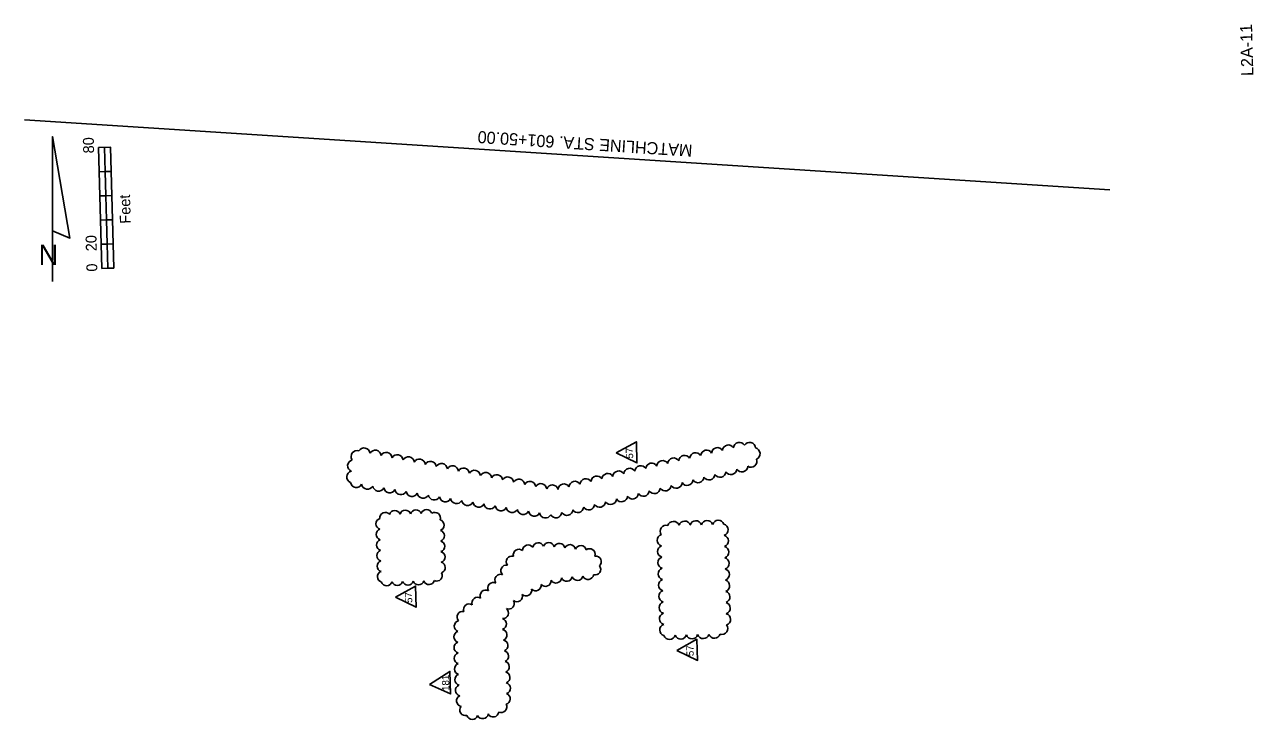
# Model space of a CAD drawing. Extents: x 928638 to 929505, y 634823 to 636085.
# Drawn here: x 928638 to 929451, y 635624 to 636085 of the extents above; entities that cross this region are included whole.
import ezdxf

# ---------------------------------------------------------------- set-up
doc = ezdxf.new("R2010")
doc.units = 0
for name, color, linetype in [('Cloud_dp', 7, 'Continuous'), ('MatchLines_dp', 7, 'Continuous'), ('NorthArw_dp', 7, 'Continuous'), ('Scale_dp', 7, 'Continuous'), ('TextShtNo', 7, 'Continuous')]:
    doc.layers.add(name, color=color, linetype=linetype)

msp = doc.modelspace()

# ---------------------------------------------------------------- linework, layer by layer
at = {"layer": 'Cloud_dp'}
for points in [[(929029.47, 635800.9), (929043.22, 635794.23), (929042.84, 635808.31)], [(928883.23, 635705.29), (928896.98, 635698.62), (928896.6, 635712.7)], [(929069.55, 635670.07), (929083.3, 635663.4), (929082.91, 635677.48)], [(928905.8, 635647.39), (928919.81, 635641.24), (928919.41, 635656.14)]]:
    msp.add_lwpolyline(points, close=True, dxfattribs=at)
for centre, radius, start, end in [((929111.02, 635803.95), 3.91, 30.8103, 175.8103), ((929117.72, 635803.92), 3.91, 3.63215, 148.63215), ((928857.83, 635798.47), 3.91, 70.45353, 215.45353), ((928862.57, 635800.26), 3.91, 6.08636, 151.08636), ((928869.88, 635798.79), 3.91, 6.08636, 151.08636), ((928877.2, 635797.31), 3.91, 6.08636, 151.08636), ((928884.51, 635795.83), 3.91, 6.08636, 151.08636), ((929081.97, 635797.08), 3.91, 30.8103, 175.8103), ((929089.24, 635798.79), 3.91, 30.8103, 175.8103), ((929096.5, 635800.51), 3.91, 30.8103, 175.8103), ((929103.76, 635802.23), 3.91, 30.8103, 175.8103), ((929120.8, 635800.34), 3.91, 292.8347, 77.8347), ((928855.54, 635792.39), 3.91, 103.22978, 248.22978), ((928891.82, 635794.36), 3.91, 6.08636, 151.08636), ((928899.14, 635792.88), 3.91, 6.08636, 151.08636), ((928906.45, 635791.4), 3.91, 6.08636, 151.08636), ((928913.77, 635789.93), 3.91, 6.08636, 151.08636), ((928921.08, 635788.45), 3.91, 6.08636, 151.08636), ((929045.67, 635788.49), 3.91, 30.8103, 175.8103), ((929052.93, 635790.2), 3.91, 30.8103, 175.8103), ((929060.19, 635791.92), 3.91, 30.8103, 175.8103), ((929067.45, 635793.64), 3.91, 30.8103, 175.8103), ((929074.71, 635795.36), 3.91, 30.8103, 175.8103), ((929112.64, 635792.24), 3.91, 211.47427, 356.47427), ((929118.68, 635795.28), 3.92, 236.84141, 21.84141), ((928854.99, 635784.95), 3.91, 103.22978, 248.22978), ((928928.39, 635786.97), 3.91, 6.08636, 151.08636), ((928935.71, 635785.5), 3.91, 6.08636, 151.08636), ((928943.02, 635784.02), 3.91, 6.08636, 151.08636), ((928950.34, 635782.54), 3.91, 6.08636, 151.08636), ((928957.65, 635781.07), 3.91, 6.08636, 151.08636), ((928964.97, 635779.59), 3.91, 6.08636, 151.08636), ((929009.36, 635779.9), 3.91, 30.8103, 175.8103), ((929016.62, 635781.62), 3.91, 30.8103, 175.8103), ((929023.88, 635783.33), 3.91, 30.8103, 175.8103), ((929031.15, 635785.05), 3.91, 30.8103, 175.8103), ((929038.41, 635786.77), 3.91, 30.8103, 175.8103), ((929083.67, 635785.04), 3.91, 211.47427, 356.47427), ((929090.91, 635786.84), 3.91, 211.47427, 356.47427), ((929098.15, 635788.64), 3.91, 211.47427, 356.47427), ((929105.39, 635790.44), 3.91, 211.47427, 356.47427), ((928857.41, 635781.88), 3.91, 188.32723, 333.32723), ((928864.77, 635780.69), 3.91, 188.32723, 333.32723), ((928872.14, 635779.5), 3.91, 188.32723, 333.32723), ((928879.51, 635778.32), 3.91, 188.32723, 333.32723), ((928886.87, 635777.13), 3.91, 188.32723, 333.32723), ((928894.24, 635775.94), 3.91, 188.32723, 333.32723), ((928972.28, 635778.11), 3.91, 6.08636, 151.08636), ((928979.59, 635776.64), 3.91, 6.08636, 151.08636), ((928987.16, 635775.72), 3.91, 15.15981, 160.15981), ((928994.84, 635776.46), 3.91, 30.8103, 175.8103), ((929002.1, 635778.18), 3.91, 30.8103, 175.8103), ((929047.47, 635776.03), 3.91, 211.47427, 356.47427), ((929054.71, 635777.83), 3.91, 211.47427, 356.47427), ((929061.95, 635779.63), 3.91, 211.47427, 356.47427), ((929069.19, 635781.43), 3.91, 211.47427, 356.47427), ((929076.43, 635783.24), 3.91, 211.47427, 356.47427), ((928901.61, 635774.75), 3.91, 188.32723, 333.32723), ((928908.97, 635773.56), 3.91, 188.32723, 333.32723), ((928916.34, 635772.37), 3.91, 188.32723, 333.32723), ((928923.7, 635771.18), 3.91, 188.32723, 333.32723), ((928931.07, 635769.99), 3.91, 188.32723, 333.32723), ((928938.44, 635768.8), 3.91, 188.32723, 333.32723), ((928945.8, 635767.61), 3.91, 188.32723, 333.32723), ((929018.5, 635768.82), 3.91, 211.47427, 356.47427), ((929025.75, 635770.62), 3.91, 211.47427, 356.47427), ((929032.99, 635772.42), 3.91, 211.47427, 356.47427), ((929040.23, 635774.23), 3.91, 211.47427, 356.47427), ((928876.53, 635757.74), 3.67, 40.04927, 185.04927), ((928882.88, 635759.09), 3.68, 19.06552, 164.06552), ((928889.88, 635759.29), 3.68, 19.06552, 164.06552), ((928896.89, 635759.48), 3.68, 19.06552, 164.06552), ((928903.9, 635759.67), 3.68, 19.06552, 164.06552), ((928909.43, 635757.83), 3.67, 339.04988, 124.04988), ((928953.17, 635766.42), 3.91, 188.32723, 333.32723), ((928960.53, 635765.23), 3.91, 188.32723, 333.32723), ((928967.9, 635764.04), 3.91, 188.32723, 333.32723), ((928975.27, 635762.85), 3.91, 188.32723, 333.32723), ((928982.63, 635761.66), 3.91, 188.32723, 333.32723), ((928989.56, 635761.79), 3.91, 208.82569, 353.82569), ((928996.78, 635763.41), 3.91, 211.47427, 356.47427), ((929004.02, 635765.22), 3.91, 211.47427, 356.47427), ((929011.26, 635767.02), 3.91, 211.47427, 356.47427), ((928874.07, 635753.94), 3.68, 109.06552, 254.06552), ((928911.85, 635752.98), 3.68, 289.06552, 74.06552), ((929062.38, 635749.03), 3.89, 71.55935, 216.55935), ((929067.36, 635751.65), 3.89, 19.06552, 164.06552), ((929074.78, 635751.86), 3.89, 19.06552, 164.06552), ((929082.21, 635752.06), 3.89, 19.06552, 164.06552), ((929089.63, 635752.26), 3.89, 19.06552, 164.06552), ((929097.06, 635752.47), 3.89, 19.06552, 164.06552), ((929099.67, 635749.99), 3.89, 289.06552, 74.06552), ((928874.26, 635746.93), 3.68, 109.06552, 254.06552), ((928874.45, 635739.93), 3.68, 109.06552, 254.06552), ((928912.05, 635745.97), 3.68, 289.06552, 74.06552), ((929060.53, 635743.03), 3.89, 109.06552, 254.06552), ((929099.87, 635742.57), 3.89, 289.06552, 74.06552), ((928874.65, 635732.92), 3.68, 109.06552, 254.06552), ((928912.24, 635738.96), 3.68, 289.06552, 74.06552), ((928912.43, 635731.95), 3.68, 289.06552, 74.06552), ((928965.05, 635733.34), 3.72, 49.30078, 194.30078), ((928971.2, 635736.19), 3.72, 35.49184, 180.49184), ((928977.88, 635737.6), 3.72, 23.24379, 168.24379), ((928984.8, 635737.8), 3.72, 15.12111, 160.12111), ((928991.79, 635737.24), 3.72, 10.70177, 155.70177), ((928998.85, 635736.43), 3.72, 11.16897, 156.16897), ((929005.98, 635735.8), 3.72, 13.75882, 158.75882), ((929011.85, 635733.72), 3.72, 342.36262, 127.36262), ((929060.73, 635735.61), 3.89, 109.06552, 254.06552), ((929100.07, 635735.14), 3.89, 289.06552, 74.06552), ((928874.84, 635725.91), 3.68, 109.06552, 254.06552), ((928912.62, 635724.94), 3.68, 289.06552, 74.06552), ((928956.82, 635722.89), 3.72, 80.82709, 225.82709), ((928960.35, 635728.86), 3.72, 72.97795, 217.97795), ((929015.84, 635728.9), 3.72, 311.70815, 96.70815), ((929060.93, 635728.18), 3.89, 109.06552, 254.06552), ((929100.28, 635727.72), 3.89, 289.06552, 74.06552), ((928875.03, 635718.9), 3.68, 109.06552, 254.06552), ((928910.63, 635719.65), 3.67, 244.72719, 29.72719), ((928952.85, 635716.76), 3.72, 68.35857, 213.35857), ((928996.71, 635719.53), 3.72, 203.69742, 348.69742), ((929003.85, 635720.11), 3.72, 200.60291, 345.60291), ((929010.82, 635720.77), 3.72, 205.2281, 350.2281), ((929015.46, 635723.73), 3.72, 254.94433, 39.94433), ((929061.14, 635720.76), 3.89, 109.06552, 254.06552), ((929100.48, 635720.29), 3.89, 289.06552, 74.06552), ((928877.49, 635716.57), 3.68, 199.06552, 344.06552), ((928884.5, 635716.76), 3.68, 199.06552, 344.06552), ((928891.51, 635716.95), 3.68, 199.06552, 344.06552), ((928898.52, 635717.14), 3.68, 199.06552, 344.06552), ((928905.53, 635717.33), 3.68, 199.06552, 344.06552), ((928948.12, 635711.36), 3.72, 64.20736, 209.20736), ((928969.8, 635709.86), 3.72, 226.75654, 11.75654), ((928976.12, 635713.21), 3.72, 224.21089, 9.21089), ((928982.66, 635716.19), 3.72, 219.75189, 4.75189), ((928989.59, 635718.36), 3.72, 209.9442, 354.9442), ((929061.34, 635713.33), 3.89, 109.06552, 254.06552), ((929100.68, 635712.87), 3.89, 289.06552, 74.06552), ((928937.64, 635701.57), 3.72, 56.11517, 201.11517), ((928943.06, 635706.29), 3.72, 60.93764, 205.93764), ((928958.26, 635701.13), 3.72, 245.70709, 30.70709), ((928963.71, 635706), 3.72, 232.91799, 17.91799), ((929061.54, 635705.91), 3.89, 109.06552, 254.06552), ((929061.74, 635698.48), 3.89, 109.06552, 254.06552), ((929100.88, 635705.45), 3.89, 289.06552, 74.06552), ((928927.79, 635692.22), 3.72, 78.08417, 223.08417), ((928932.05, 635697.16), 3.72, 55.40174, 200.40174), ((928954.38, 635694.84), 3.72, 265.96014, 50.96014), ((929061.95, 635691.06), 3.89, 109.06552, 254.06552), ((929101.09, 635698.02), 3.89, 289.06552, 74.06552), ((929101.29, 635690.6), 3.89, 289.06552, 74.06552), ((928925.99, 635686.07), 3.72, 104.18139, 249.18139), ((928953.07, 635687.56), 3.72, 288.59197, 73.59197), ((929062.15, 635683.63), 3.89, 109.06552, 254.06552), ((929099.44, 635684.6), 3.89, 251.55935, 36.55935), ((928925.77, 635679.03), 3.72, 107.25231, 252.25231), ((928953.44, 635680.39), 3.72, 292.37351, 77.37351), ((929064.76, 635681.16), 3.89, 199.06552, 344.06552), ((929072.19, 635681.37), 3.89, 199.06552, 344.06552), ((929079.61, 635681.57), 3.89, 199.06552, 344.06552), ((929087.04, 635681.77), 3.89, 199.06552, 344.06552), ((929094.46, 635681.97), 3.89, 199.06552, 344.06552), ((928925.79, 635671.95), 3.72, 108.1911, 253.1911), ((928954.01, 635673.33), 3.72, 291.79029, 76.79029), ((928954.52, 635666.25), 3.72, 291.39534, 76.39534), ((928925.91, 635664.86), 3.72, 108.70236, 253.70236), ((928926.08, 635657.76), 3.72, 109.08693, 254.08693), ((928954.98, 635659.17), 3.72, 291.10502, 76.10502), ((928926.34, 635650.68), 3.72, 109.98189, 254.98189), ((928955.4, 635652.09), 3.72, 290.67805, 75.67805), ((928926.74, 635643.62), 3.72, 111.56299, 256.56299), ((928955.68, 635645.03), 3.72, 288.88082, 73.88082), ((928927.44, 635636.62), 3.72, 114.83706, 259.83706), ((928955.59, 635638.01), 3.72, 284.66878, 69.66878), ((928929.64, 635630.57), 3.73, 140.1104, 285.1104), ((928948.04, 635629.67), 3.73, 207.44055, 352.44055), ((928953.31, 635632.55), 3.72, 244.93463, 29.93463), ((928934.17, 635628.06), 3.72, 197.04995, 342.04995), ((928941.06, 635628.54), 3.72, 205.91527, 350.91527)]:
    msp.add_arc(centre, radius, start, end, dxfattribs=at)
at = {"layer": 'MatchLines_dp'}
msp.add_lwpolyline([(929356.28, 635975.21), (928997.02, 635998.35), (928637.76, 636021.48)], dxfattribs=at)
at = {"layer": 'NorthArw_dp'}
msp.add_line((928656.21, 635914.42), (928656.21, 636010.42), dxfattribs=at)
msp.add_lwpolyline([(928656.21, 635948.02), (928656.21, 636010.42), (928667.73, 635943.22)], close=True, dxfattribs=at)
at = {"layer": 'Scale_dp'}
for p, q in [((928694.72, 636003.32), (928686.73, 636003.1)), ((928686.73, 636003.1), (928688.91, 635923.13)), ((928696.91, 635923.35), (928694.72, 636003.32)), ((928688.91, 635923.13), (928696.91, 635923.35))]:
    msp.add_line(p, q, dxfattribs=at)
for points in [[(928695.16, 635987.32), (928691.16, 635987.21), (928690.73, 636003.21), (928694.72, 636003.32)], [(928691.6, 635971.22), (928687.6, 635971.11), (928687.17, 635987.1), (928691.16, 635987.21)], [(928696.04, 635955.33), (928692.04, 635955.23), (928691.6, 635971.22), (928695.6, 635971.33)], [(928692.47, 635939.23), (928688.48, 635939.12), (928688.04, 635955.12), (928692.04, 635955.23)], [(928696.91, 635923.35), (928692.91, 635923.24), (928692.47, 635939.23), (928696.47, 635939.34)]]:
    msp.add_lwpolyline(points, close=True, dxfattribs=at)

# ---------------------------------------------------------------- texts
at = {"layer": 'Cloud_dp'}
for s, p in [('57', (929040.73, 635797.15)), ('57', (928894.49, 635701.54)), ('57', (929080.81, 635666.32)), ('181', (928919.02, 635643.31))]:
    msp.add_text(s, height=4.8, rotation=91.56552, dxfattribs=at).set_placement(p)
at = {"layer": 'MatchLines_dp'}
msp.add_text('MATCHLINE STA. 601+50.00', height=8, rotation=176.31552, dxfattribs=at).set_placement((929080.13, 636005.02))
at = {"layer": 'NorthArw_dp'}
msp.add_text('N', height=13.43, dxfattribs=at).set_placement((928647.09, 635925.28))
at = {"layer": 'Scale_dp'}
for s, p in [('80', (928683.83, 635999.37)), ('Feet', (928708.11, 635952.81)), ('20', (928685.6, 635934.54)), ('0', (928685.97, 635921.06))]:
    msp.add_text(s, height=7.2, rotation=91.56552, dxfattribs=at).set_placement(p)
at = {"layer": 'TextShtNo'}
msp.add_text('L2A-11', height=8, rotation=91.56552, dxfattribs=at).set_placement((929451.35, 636050.64))

doc.saveas('drawing.dxf')
